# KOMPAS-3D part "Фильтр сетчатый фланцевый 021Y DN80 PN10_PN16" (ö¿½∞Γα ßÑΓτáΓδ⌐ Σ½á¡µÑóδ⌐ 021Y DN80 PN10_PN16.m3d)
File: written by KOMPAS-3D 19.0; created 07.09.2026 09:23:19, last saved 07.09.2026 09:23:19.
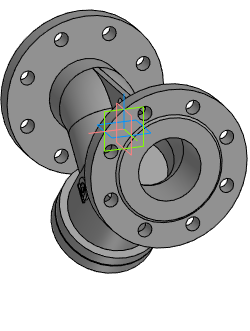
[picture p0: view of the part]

Document properties: Автор: Энергия; Полное имя файла: Z:\3.Личные\sachek\Dendor\_3D для проектировщиков\8.3 Фильтр сетчатый 021Y\021Y_STP\Фильтр сетчатый фланцевый 021Y DN80 PN10_PN16.m3d

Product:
- Part/product: Фильтр сетчатый фланцевый 021Y DN80 PN10_PN16

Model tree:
1. Операция без истории:1  (labels: Фильтр сетчатый фланцевый 021Y DN80 PN10_PN16)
